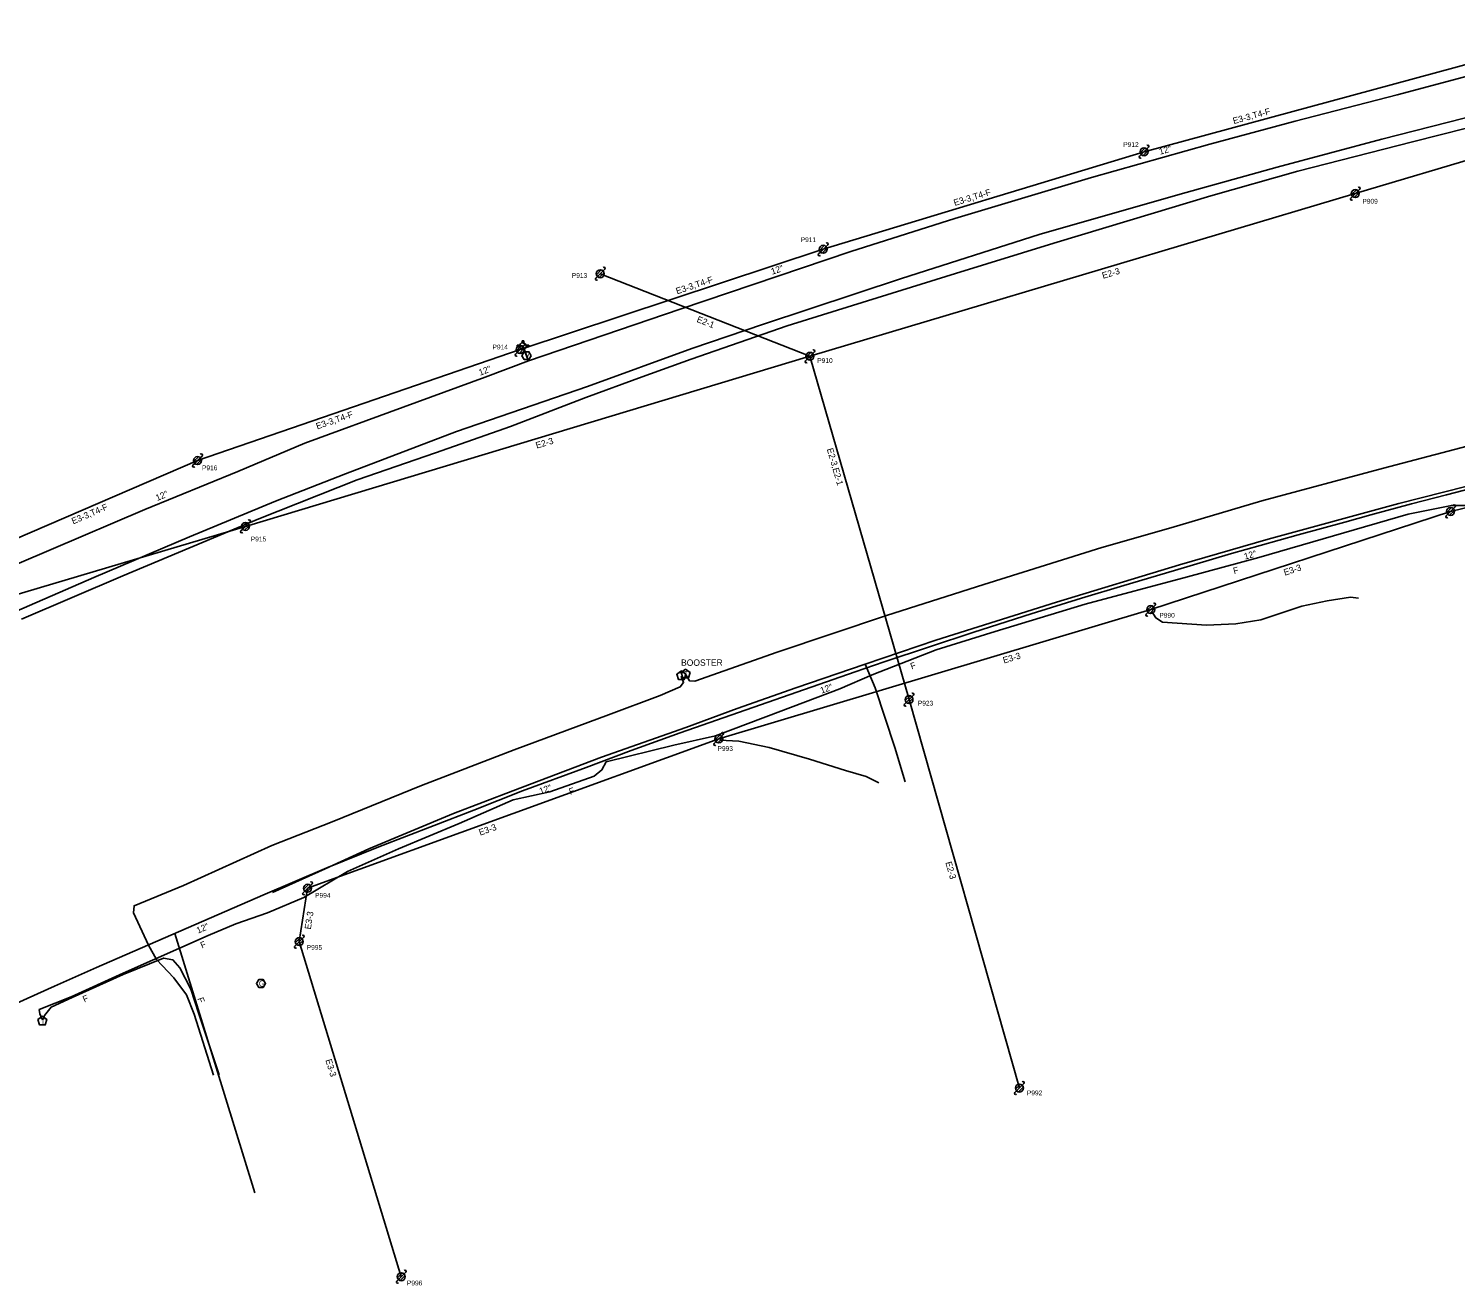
# Model space of a CAD drawing. Extents: x 1741604 to 1825760, y 1164229 to 1194908.
# Drawn here: x 1796131 to 1797026, y 1187521 to 1188310 of the extents above; entities that cross this region are included whole.
import ezdxf

# ---------------------------------------------------------------- set-up
doc = ezdxf.new("R2010")
doc.units = 0
for name, color, linetype in [('RD_EX_SU_Elec', 7, 'Continuous'), ('RD_EX_SU_Gas', 7, 'Continuous'), ('RD_EX_SU_H2O', 7, 'Continuous'), ('RD_EX_SU_Ovhd', 7, 'Continuous'), ('RD_EX_SU_Pole', 7, 'Continuous'), ('RD_EX_SU_Telecom', 7, 'Continuous'), ('RD_EX_SU_TX_H2O', 7, 'Continuous'), ('RD_EX_SU_TX_Pole', 7, 'Continuous'), ('RD_EX_SU_TX_Telecom', 7, 'Continuous')]:
    doc.layers.add(name, color=color, linetype=linetype)

# ---------------------------------------------------------------- blocks, each defined once
blk = doc.blocks.new('SUE_TPP')
at = {"layer": 'RD_EX_SU_Telecom'}
blk.add_lwpolyline([(0, 3), (-2.85, 0.93), (-1.76, -2.43), (1.76, -2.43), (2.85, 0.93)], close=True, dxfattribs=at)
blk.add_text('T', height=3.75, dxfattribs=at).set_placement((-1.25, -1.88))
blk = doc.blocks.new('SUE_GVC')
at = {"layer": 'RD_EX_SU_Gas'}
blk.add_lwpolyline([(1.44, -2.5), (2.89, 0), (1.44, 2.5), (-1.44, 2.5), (-2.89, 0), (-1.44, -2.5)], close=True, dxfattribs=at)
blk.add_text('G', height=3.75, dxfattribs=at).set_placement((-1.34, -1.88))
blk = doc.blocks.new('SUE_WFH')
at = {"layer": 'RD_EX_SU_H2O'}
for p, q in [((-2.01, 0.6), (-3.65, 0.6)), ((-3.65, 0.6), (-3.65, -0.45)), ((-0.48, 3.38), (-0.48, 2.04)), ((0.57, 3.38), (-0.48, 3.38)), ((0.57, 2.02), (0.57, 3.38)), ((3.7, 0.6), (2.01, 0.6)), ((3.7, -0.45), (3.7, 0.6)), ((-3.65, -0.45), (-2.05, -0.45)), ((2.05, -0.45), (3.7, -0.45))]:
    blk.add_line(p, q, dxfattribs=at)
for radius in [2.1, 0.263]:
    blk.add_circle((0, 0), radius, dxfattribs=at)
for start, end in [(163.3387, 192.31502), (74.24552, 103.21276), (347.68498, 16.6613)]:
    blk.add_arc((0, 0), 2.1, start, end, dxfattribs=at)
blk = doc.blocks.new('SUE_WV')
at = {"layer": 'RD_EX_SU_H2O'}
blk.add_lwpolyline([(2.89, 0), (1.44, 2.5), (-1.44, 2.5), (-2.89, 0), (-1.44, -2.5), (1.44, -2.5)], close=True, dxfattribs=at)
blk.add_text('V', height=3.75, dxfattribs=at).set_placement((-1.43, -1.88))
blk = doc.blocks.new('SUE_PP')
at = {"layer": 'RD_EX_SU_Pole'}
for p, q in [((-2.41, -0.65), (0.65, 2.41)), ((-1.77, -1.77), (1.77, 1.77)), ((-0.65, -2.41), (2.41, 0.65)), ((1.77, 1.77), (2.83, 2.83)), ((-2.83, -2.83), (-1.77, -1.77))]:
    blk.add_line(p, q, dxfattribs=at)
blk.add_circle((0, 0), 2.5, dxfattribs=at)
for centre, start, end in [((2.3, 3.36), 315, 135), ((-2.3, -3.36), 135, 315)]:
    blk.add_arc(centre, 0.75, start, end, dxfattribs=at)

msp = doc.modelspace()

# ---------------------------------------------------------------- linework, layer by layer
at = {"layer": 'RD_EX_SU_Elec'}
for points in [[(1796835.73, 1187944.21), (1796838.24, 1187940.16), (1796842.5, 1187937.37), (1796870.05, 1187935.56), (1796888.61, 1187936.35), (1796904.27, 1187938.85), (1796930, 1187947.41), (1796945.73, 1187950.81), (1796960.5, 1187953.11), (1796965.4, 1187952.56)], [(1796564.98, 1187863.44), (1796576.77, 1187862.75), (1796595.77, 1187858.77), (1796621.04, 1187851.57), (1796643.67, 1187844.5), (1796656.73, 1187840.57), (1796664.71, 1187836.76)]]:
    msp.add_lwpolyline(points, dxfattribs=at)
at = {"layer": 'RD_EX_SU_Gas'}
for points in [[(1796126.94, 1187939.39), (1796190.37, 1187966.63), (1796275.76, 1188002.28), (1796337.44, 1188026.79), (1796386.52, 1188043.75), (1796433.69, 1188060.18), (1796480.9, 1188078.3), (1796516.28, 1188091.42), (1796546.96, 1188102.39), (1796607.19, 1188123.38), (1796657.61, 1188139.1), (1796712.6, 1188156.15), (1796774.42, 1188175.17), (1796822.26, 1188189.61), (1796872.88, 1188204.94), (1796927.34, 1188220.34), (1796999.22, 1188238.71), (1797050.44, 1188251.64)], [(1796656.1, 1187911.21), (1796700.26, 1187926.24), (1796776.05, 1187949.97), (1796853.24, 1187973.45), (1796908.86, 1187989.52), (1796990.78, 1188011.87), (1797073.97, 1188032.99), (1797158.33, 1188053.63), (1797222.98, 1188067.43), (1797327.66, 1188089.58), (1797395.86, 1188103.05), (1797465.31, 1188115.89), (1797490.6, 1188120.59), (1797504.29, 1188121.55), (1797523.16, 1188120.37), (1797539.47, 1188121.55), (1797556.07, 1188120.37), (1797575.66, 1188121.89)], [(1796284.34, 1187767.88), (1796317.46, 1187782.66), (1796344.7, 1187795.26), (1796397.89, 1187817.55), (1796435.11, 1187831.76), (1796490.64, 1187852.7), (1796543.52, 1187871.4), (1796575.87, 1187883.32), (1796612.49, 1187896.37), (1796656.1, 1187911.21)], [(1796656.1, 1187911.21), (1796662.3, 1187896.24), (1796674.64, 1187858.84), (1796681.22, 1187837.43)]]:
    msp.add_lwpolyline(points, dxfattribs=at)
at = {"layer": 'RD_EX_SU_H2O'}
msp.add_line((1796223.11, 1187742.29), (1796273.17, 1187579.57), dxfattribs=at)
for points in [[(1796441.83, 1188109.93), (1796444.87, 1188101.29), (1796539.94, 1188133.72), (1796647.13, 1188169.94), (1796712.18, 1188190.57), (1796798.06, 1188216.42), (1796872.26, 1188237.32), (1796925.71, 1188251.76), (1796989.63, 1188268.23), (1797072.11, 1188290.16), (1797127.52, 1188303.54), (1797152.28, 1188309.78)], [(1796204.27, 1188008.11), (1796262.7, 1188031.92), (1796304.64, 1188049.75), (1796366.26, 1188072.39), (1796417.64, 1188091.03), (1796444.87, 1188101.29)], [(1796649.84, 1187906.33), (1796667.87, 1187912.5), (1796696.35, 1187922.04), (1796724.15, 1187931.17), (1796760.05, 1187942.67), (1796791.63, 1187952.42), (1796818.3, 1187960.45), (1796850.05, 1187969.91), (1796885.9, 1187980.56), (1796903.78, 1187985.54), (1796927.57, 1187992.31), (1796956.84, 1188000.11), (1796973.28, 1188004.7), (1796998.71, 1188011.64), (1797020.74, 1188017.27), (1797050.38, 1188025.03)], [(1795893.48, 1187869.47), (1795976.99, 1187908.33), (1796032.87, 1187934.75), (1796086.58, 1187957.92), (1796204.27, 1188008.11)], [(1796278.22, 1187766.25), (1796318.34, 1187783.49), (1796351.08, 1187796.53), (1796385.64, 1187809.94), (1796410.51, 1187819.66), (1796441.19, 1187831.72), (1796481.15, 1187846.24), (1796509.2, 1187856.9), (1796540, 1187868.07), (1796649.84, 1187906.33)], [(1796117.41, 1187695.58), (1796147.64, 1187709.19), (1796173.99, 1187720.93), (1796278.22, 1187766.25)]]:
    msp.add_lwpolyline(points, dxfattribs=at)
at = {"layer": 'RD_EX_SU_Ovhd'}
for p, q in [((1796963.44, 1188206.26), (1797309.7, 1188309.3)), ((1796830.97, 1188232.5), (1797039.93, 1188289.19)), ((1796629.71, 1188171.31), (1796830.97, 1188232.5)), ((1796621.4, 1188104.2), (1796963.44, 1188206.26)), ((1796439.62, 1188108.38), (1796629.71, 1188171.31)), ((1796489.91, 1188156.02), (1796621.4, 1188104.2)), ((1796237.3, 1188038.84), (1796439.62, 1188108.38)), ((1796267.41, 1187997.51), (1796621.4, 1188104.2)), ((1796621.4, 1188104.2), (1796683.54, 1187888.91)), ((1797023.16, 1188006.96), (1797208.33, 1188051.07)), ((1796111.99, 1187984.95), (1796237.3, 1188038.84)), ((1796835.13, 1187945.34), (1797023.16, 1188006.96)), ((1795855.16, 1187874.79), (1796267.41, 1187997.51)), ((1796564.24, 1187864.21), (1796835.13, 1187945.34)), ((1796683.54, 1187888.91), (1796752.76, 1187645.27)), ((1796306.31, 1187770.59), (1796564.24, 1187864.21)), ((1796301.13, 1187737.12), (1796306.31, 1187770.59)), ((1796301.13, 1187737.12), (1796365.13, 1187526.97))]:
    msp.add_line(p, q, dxfattribs=at)
at = {"layer": 'RD_EX_SU_Pole'}
for p, q in [((1796828.15, 1188229.67), (1796829.21, 1188230.74)), ((1796828.56, 1188231.86), (1796831.62, 1188234.92)), ((1796829.21, 1188230.74), (1796832.74, 1188234.27)), ((1796830.33, 1188230.09), (1796833.39, 1188233.15)), ((1796832.74, 1188234.27), (1796833.8, 1188235.33)), ((1796960.62, 1188203.43), (1796961.68, 1188204.49)), ((1796961.03, 1188205.62), (1796964.09, 1188208.68)), ((1796961.68, 1188204.49), (1796965.21, 1188208.03)), ((1796962.8, 1188203.85), (1796965.86, 1188206.91)), ((1796965.21, 1188208.03), (1796966.27, 1188209.09)), ((1796627.3, 1188170.66), (1796630.36, 1188173.73)), ((1796631.48, 1188173.08), (1796632.54, 1188174.14)), ((1796626.88, 1188168.48), (1796627.94, 1188169.54)), ((1796627.94, 1188169.54), (1796631.48, 1188173.08)), ((1796629.06, 1188168.9), (1796632.13, 1188171.96)), ((1796487.49, 1188155.37), (1796490.55, 1188158.43)), ((1796488.14, 1188154.25), (1796491.67, 1188157.78)), ((1796489.26, 1188153.6), (1796492.32, 1188156.66)), ((1796491.67, 1188157.78), (1796492.73, 1188158.85)), ((1796487.08, 1188153.19), (1796488.14, 1188154.25)), ((1796441.39, 1188110.14), (1796442.45, 1188111.2)), ((1796436.79, 1188105.55), (1796437.85, 1188106.61)), ((1796437.21, 1188107.73), (1796440.27, 1188110.79)), ((1796437.85, 1188106.61), (1796441.39, 1188110.14)), ((1796438.97, 1188105.96), (1796442.04, 1188109.02)), ((1796618.57, 1188101.37), (1796619.63, 1188102.43)), ((1796618.98, 1188103.55), (1796622.04, 1188106.62)), ((1796619.63, 1188102.43), (1796623.16, 1188105.97)), ((1796620.75, 1188101.79), (1796623.81, 1188104.85)), ((1796623.16, 1188105.97), (1796624.22, 1188107.03)), ((1796234.89, 1188038.2), (1796237.95, 1188041.26)), ((1796235.54, 1188037.08), (1796239.07, 1188040.61)), ((1796236.66, 1188036.43), (1796239.72, 1188039.49)), ((1796239.07, 1188040.61), (1796240.13, 1188041.67)), ((1796234.47, 1188036.01), (1796235.54, 1188037.08)), ((1797020.34, 1188004.13), (1797021.4, 1188005.19)), ((1797020.75, 1188006.31), (1797023.81, 1188009.37)), ((1797021.4, 1188005.19), (1797024.93, 1188008.72)), ((1797022.52, 1188004.54), (1797025.58, 1188007.6)), ((1797024.93, 1188008.72), (1797025.99, 1188009.78)), ((1796264.58, 1187994.68), (1796265.64, 1187995.74)), ((1796264.99, 1187996.86), (1796268.05, 1187999.92)), ((1796265.64, 1187995.74), (1796269.17, 1187999.28)), ((1796266.76, 1187995.09), (1796269.82, 1187998.16)), ((1796269.17, 1187999.28), (1796270.24, 1188000.34)), ((1796832.3, 1187942.51), (1796833.36, 1187943.57)), ((1796832.72, 1187944.7), (1796835.78, 1187947.76)), ((1796833.36, 1187943.57), (1796836.9, 1187947.11)), ((1796834.49, 1187942.93), (1796837.55, 1187945.99)), ((1796836.9, 1187947.11), (1796837.96, 1187948.17)), ((1796681.12, 1187888.26), (1796684.18, 1187891.32)), ((1796681.77, 1187887.14), (1796685.3, 1187890.67)), ((1796682.89, 1187886.49), (1796685.95, 1187889.55)), ((1796685.3, 1187890.67), (1796686.36, 1187891.73)), ((1796680.71, 1187886.08), (1796681.77, 1187887.14)), ((1796561.41, 1187861.38), (1796562.47, 1187862.45)), ((1796561.83, 1187863.57), (1796564.89, 1187866.63)), ((1796562.47, 1187862.45), (1796566.01, 1187865.98)), ((1796563.59, 1187861.8), (1796566.66, 1187864.86)), ((1796566.01, 1187865.98), (1796567.07, 1187867.04)), ((1796303.89, 1187769.95), (1796306.95, 1187773.01)), ((1796304.54, 1187768.83), (1796308.07, 1187772.36)), ((1796305.66, 1187768.18), (1796308.72, 1187771.24)), ((1796308.07, 1187772.36), (1796309.13, 1187773.42)), ((1796303.48, 1187767.77), (1796304.54, 1187768.83)), ((1796298.3, 1187734.29), (1796299.37, 1187735.35)), ((1796298.72, 1187736.47), (1796301.78, 1187739.54)), ((1796299.37, 1187735.35), (1796302.9, 1187738.89)), ((1796300.49, 1187734.71), (1796303.55, 1187737.77)), ((1796302.9, 1187738.89), (1796303.96, 1187739.95))]:
    msp.add_line(p, q, dxfattribs=at)
for centre in [(1796830.97, 1188232.5), (1796963.44, 1188206.26), (1796629.71, 1188171.31), (1796489.91, 1188156.02), (1796439.62, 1188108.38), (1796621.4, 1188104.2), (1796237.3, 1188038.84), (1797023.16, 1188006.96), (1796267.41, 1187997.51), (1796835.13, 1187945.34), (1796683.54, 1187888.91), (1796564.24, 1187864.21), (1796306.31, 1187770.59), (1796301.13, 1187737.12)]:
    msp.add_circle(centre, 2.5, dxfattribs=at)
for centre, start, end in [((1796833.27, 1188235.86), 315, 135), ((1796828.68, 1188229.14), 135, 315), ((1796965.74, 1188209.62), 315, 135), ((1796961.15, 1188202.9), 135, 315), ((1796632.01, 1188174.67), 315, 135), ((1796627.41, 1188167.95), 135, 315), ((1796492.2, 1188159.38), 315, 135), ((1796487.61, 1188152.66), 135, 315), ((1796441.92, 1188111.73), 315, 135), ((1796437.32, 1188105.02), 135, 315), ((1796623.69, 1188107.56), 315, 135), ((1796619.1, 1188100.84), 135, 315), ((1796239.6, 1188042.2), 315, 135), ((1796235.01, 1188035.48), 135, 315), ((1797020.87, 1188003.6), 135, 315), ((1797025.46, 1188010.31), 315, 135), ((1796265.11, 1187994.15), 135, 315), ((1796269.71, 1188000.87), 315, 135), ((1796832.83, 1187941.98), 135, 315), ((1796837.43, 1187948.7), 315, 135), ((1796685.83, 1187892.26), 315, 135), ((1796681.24, 1187885.55), 135, 315), ((1796561.94, 1187860.85), 135, 315), ((1796566.54, 1187867.57), 315, 135), ((1796308.6, 1187773.95), 315, 135), ((1796304.01, 1187767.24), 135, 315), ((1796303.43, 1187740.48), 315, 135), ((1796298.84, 1187733.76), 135, 315)]:
    msp.add_arc(centre, 0.75, start, end, dxfattribs=at)
at = {"layer": 'RD_EX_SU_Telecom'}
for points in [[(1796114.26, 1187940.19), (1796172.33, 1187965.47), (1796232.32, 1187990.96), (1796286.14, 1188013.28), (1796330.03, 1188030.46), (1796399.84, 1188056.99), (1796481.96, 1188085.26), (1796547.42, 1188109.16), (1796592.22, 1188124.3), (1796678.84, 1188153.05), (1796765.24, 1188180.55), (1796853.6, 1188205.82), (1796914.38, 1188222.74), (1796980.05, 1188240.41), (1797062.85, 1188261.56)], [(1796543.44, 1187904.9), (1796545.86, 1187900.72), (1796549.28, 1187900.54), (1796600.93, 1187918.63), (1796669.43, 1187941.72), (1796730.43, 1187961.19), (1796804.46, 1187984.36), (1796847.66, 1187996.63), (1796904.8, 1188013.65), (1796981.04, 1188034.01), (1797045.59, 1188050.89)], [(1796140.16, 1187688.03), (1796138.48, 1187691.9), (1796138.07, 1187694.51), (1796158.13, 1187702.42), (1796190.77, 1187717.34), (1796243.97, 1187740.98), (1796261.35, 1187748.26), (1796281.3, 1187755.26), (1796304.06, 1187764.69), (1796331.29, 1187781.07), (1796363.35, 1187795.26), (1796401.4, 1187811.18), (1796435.27, 1187826.14), (1796458.29, 1187830.99), (1796486.11, 1187840.84), (1796490.99, 1187844.77), (1796493.54, 1187849.82), (1796536.02, 1187860.25), (1796562.22, 1187866.1), (1796603.15, 1187881.64), (1796640.06, 1187895.58), (1796660.4, 1187904.51), (1796700.5, 1187920.1), (1796737.55, 1187931.54), (1796794.1, 1187948.7), (1796858.13, 1187965.92), (1796902.85, 1187977.93), (1796996.7, 1188005.13), (1797023.77, 1188010.64), (1797037.78, 1188010.54)], [(1796247.4, 1187653.4), (1796235.27, 1187691.59), (1796230.31, 1187703.79), (1796222.46, 1187714.35), (1796211.54, 1187725.95), (1796206.49, 1187734.96), (1796197.15, 1187755.27), (1796197.52, 1187759.63), (1796228.62, 1187772.22), (1796283.96, 1187797.47), (1796321.73, 1187812.16), (1796377.72, 1187834.93), (1796435.86, 1187857.32), (1796495.15, 1187879.35), (1796527.48, 1187891.43), (1796540.08, 1187896.83), (1796542.19, 1187899.56), (1796540.7, 1187903.56)], [(1796140.78, 1187688.24), (1796141.29, 1187690.86), (1796145.47, 1187696.07), (1796158.79, 1187702.01), (1796190.59, 1187716.55), (1796216, 1187726.77), (1796221.88, 1187725.67), (1796226.21, 1187720.74), (1796233.04, 1187707.34), (1796238.24, 1187691.88), (1796250.98, 1187653.55)]]:
    msp.add_lwpolyline(points, dxfattribs=at)

# ---------------------------------------------------------------- block references
at = {"layer": 'RD_EX_SU_Gas'}
msp.add_blockref('SUE_GVC', (1796277.11, 1187710.84), dxfattribs=at)
at = {"layer": 'RD_EX_SU_H2O'}
for name, p in [('SUE_WFH', (1796441.36, 1188110.63)), ('SUE_WV', (1796443.7, 1188104.61))]:
    msp.add_blockref(name, p, dxfattribs=at)
at = {"layer": 'RD_EX_SU_Pole'}
for p in [(1796752.76, 1187645.27), (1796365.13, 1187526.97)]:
    msp.add_blockref('SUE_PP', p, dxfattribs=at)
at = {"layer": 'RD_EX_SU_Telecom'}
for p in [(1796540.77, 1187903.87), (1796543.43, 1187904.9), (1796140.06, 1187687.27)]:
    msp.add_blockref('SUE_TPP', p, dxfattribs=at)

# ---------------------------------------------------------------- texts
at = {"layer": 'RD_EX_SU_Ovhd'}
for s, rotation, p in [('E3-3,T4-F', 15.1785, (1796887.25, 1188249.84)), ('E3-3,T4-F', 16.91141, (1796712.21, 1188198.48)), ('E2-3', 16.61407, (1796805.28, 1188152.81)), ('E3-3,T4-F', 18.31864, (1796538.11, 1188143.09)), ('E2-1', 338.49268, (1796550.04, 1188125.87)), ('E3-3,T4-F', 18.96682, (1796312.43, 1188058.32)), ('E2-3', 16.77279, (1796450.07, 1188046.3)), ('E2-3,E2-1', 286.09944, (1796631.95, 1188046)), ('E3-3,T4-F', 23.27152, (1796159.34, 1187998.78)), ('E3-3', 18.14262, (1796919.25, 1187966.59)), ('E3-3', 16.6725, (1796743.12, 1187911.52)), ('E3-3', 19.94843, (1796414.61, 1187803.52)), ('E2-3', 285.86132, (1796706.33, 1187786.73)), ('E3-3', 81.21638, (1796308.36, 1187744.57)), ('E3-3', 286.93666, (1796317.5, 1187662.78))]:
    msp.add_text(s, height=4, rotation=rotation, dxfattribs=at).set_placement(p)
at = {"layer": 'RD_EX_SU_TX_H2O'}
for rotation, p in [(15.73007, (1796840.97, 1188230.58)), (18.67012, (1796597.75, 1188155.36)), (20.6382, (1796414.55, 1188092)), (22.1698, (1796212.01, 1188013.42)), (15.55692, (1796894.25, 1187976.66)), (19.209, (1796628.64, 1187892.59)), (19.95939, (1796452.45, 1187829.43)), (23.49742, (1796237.68, 1187742.08))]:
    msp.add_text('12"', height=4, rotation=rotation, dxfattribs=at).set_placement(p)
at = {"layer": 'RD_EX_SU_TX_Pole'}
for s, p in [('P912', (1796817.91, 1188235.5)), ('P909', (1796967.89, 1188199.96)), ('P911', (1796615.63, 1188175.86)), ('P913', (1796472.06, 1188153.42)), ('P914', (1796422.32, 1188108.53)), ('P910', (1796626.01, 1188100.07)), ('P916', (1796240.12, 1188032.74)), ('P915', (1796270.72, 1187988.11)), ('P990', (1796840.56, 1187940.29)), ('P923', (1796689.08, 1187885.18)), ('P993', (1796563.43, 1187856.72)), ('P994', (1796311.06, 1187764.62)), ('P995', (1796305.81, 1187731.97)), ('P992', (1796757.46, 1187640.72)), ('P996', (1796368.65, 1187521.51))]:
    msp.add_text(s, height=3, dxfattribs=at).set_placement(p)
at = {"layer": 'RD_EX_SU_TX_Telecom'}
for rotation, p in [(15.03951, (1796887.45, 1187967.58)), (21.24529, (1796685.29, 1187907.75)), (19.50265, (1796471.07, 1187829.15)), (23.96205, (1796240.16, 1187732.72)), (24.56658, (1796166.38, 1187698.89)), (288.60194, (1796237.15, 1187701.4))]:
    msp.add_text('F', height=4, rotation=rotation, dxfattribs=at).set_placement(p)
msp.add_text('BOOSTER', height=4, dxfattribs=at).set_placement((1796540.56, 1187910.1))

doc.saveas('drawing.dxf')
